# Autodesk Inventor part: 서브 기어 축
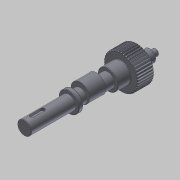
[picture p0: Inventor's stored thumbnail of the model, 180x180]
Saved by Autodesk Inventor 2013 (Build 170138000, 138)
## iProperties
Created: 2018-12
Part Number: 서브 기어 축
Material: 강철, 연강
Document SubType Name: Modeling
Designer: mduedu
Categories: <?xml version="1.0" encoding="UTF-16"?> <MemberInstance><Categories><FamilyTemplate><FamilyTemplateParameter ValueType="xs:double" Id="1" ObjectReferenceKey="da
Density: 1 g/cm^3
Author: mduedu
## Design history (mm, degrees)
sketch "Sketch1"
  geometry: C1 r 21.3 at (0, 0)
  constraints: 1 centre point
  dimensions: "d0" = 42.6 diameter of C1 (= da_da)
extrude "Extrusion1" new body sketch "Sketch1" distance "d1" = 20 (= da_b); taper "d2" = 0 deg
workplane "Work Plane2"
sketch "Sketch2"
  geometry: C1 r 21.3 at (0, 0) reference; C2 r 20.5 at (0, 0)
  constraints: 1 centre point, 1 coincident
  dimensions: "d3" = 41 diameter of C2 (= da_dw)
feature "피치 지름" sketch "Sketch2" dims "d4" = 10, "d5" = 0
workplane "Work Plane8"
workplane "Work Plane9"
chamfer "모따기1" distance "d49" = 1; stored, may be unused: second distance "d50" = 2, angle "d51" = 45 deg
sketch "스케치3"
  geometry: C1 r 12.5 at (0, 0); 1 further point
  constraints: 1 centre point, 1 coincident
  dimensions: "d52" = 25 diameter of C1
extrude "돌출2" join sketch "스케치3" distance "d53" = 16; taper "d54" = 0 deg
sketch "스케치4"
  geometry: C1 r 8.5 at (0, 0); 1 further point
  constraints: 1 centre point, 1 coincident
  dimensions: "d55" = 17 diameter of C1
extrude "돌출3" join sketch "스케치4" distance "d56" = 103; taper "d57" = 0 deg
sketch "스케치5"
  geometry: C1 r 7.5 at (0, 0); 1 further point
  constraints: 1 centre point, 1 coincident
  dimensions: "d58" = 15 diameter of C1
extrude "돌출4" join sketch "스케치5" distance "d59" = 16; taper "d60" = 0 deg
sketch "스케치6"
  geometry: C1 r 4 at (0, 0); 1 further point
  constraints: 1 centre point, 1 coincident
  dimensions: "d61" = 8 diameter of C1
extrude "돌출5" join sketch "스케치6" distance "d62" = 7; taper "d63" = 0 deg
chamfer "모따기2" distance "d64" = 0.5; stored, may be unused: second distance "d65" = 2, angle "d66" = 45 deg
fillet "모깎기1" dims "d67" = 0.5
feature "스퍼 기어" dims "da_b" = 20, "da_d" = 41, "da_aw" = 31, "da_da" = 42.6, "da_df" = 39.086, "da_dw" = 41, angle "da_beta" = 0 deg, "da_lefttooth" = 0, "da_righttooth" = 0
node "작업 평면11"
sketch "스케치7"
  geometry: C1 r 11.5 at (0, 3); C2 r 8.5 at (0, 0) reference; 1 further point
  constraints: 1 centre point, 1 tangent, 1 vertical alignment
  dimensions: "d69" = 3 distance of point (0, 0) C1.centre; "d70" = 23 diameter of C1 (derived)
extrude "돌출6" join sketch "스케치7" stored distance "d71" = 20; taper "d72" = 0 deg
node "작업 평면12"
sketch "스케치8"
  geometry: C1 r 12.5 at (0, 0) reference; C2 r 12.5 at (0, 0) reference; 1 further point
extrude "돌출7" join sketch "스케치8" distance "d74" = 5; taper "d75" = 0 deg
chamfer "모따기3" distance "d76" = 0.5; stored, may be unused: second distance "d77" = 2, angle "d78" = 45 deg
sketch "스케치9"
  geometry: L1 (-8, 139)-(8, 139) reference; L2 (0, 139)-(0, 0); L3 (-8.5, 84)-(-8.5, 138.5) reference; L4 (-8.5, 115)-(0, 115); L5 (-8.5, 115)-(-8.5, 113.5); L6 (-8.5, 113.5)-(-7, 115); L7 (-7, 115)-(-8.5, 115)
  constraints: 10 end point, 4 point on line, 2 perpendicular, 1 collinear, 1 midpoint
  dimensions: "d79" = 24 distance between parallel lines of L4 L1; "d80" = 3 diameter of L5.end L4; "d81" = 45 deg angle of L6 L3
revolve "회전1" sketch "스케치9" stored, may be unused: angle "d82" = 90 deg
sketch "스케치10"
  geometry: L1 (-8.5, 116.5)-(-7, 115) reference; L2 (-8.5, 113.5)-(-7, 115) reference; 2 further points
  constraints: 1 coincident
node "작업점1"
node "작업 평면13"
sketch "스케치11"
  geometry: L1 (-2.5, 93.5)-(-2.5, 80.5); L2 (2.5, 80.5)-(2.5, 93.5); L3 (-8, 103)-(8, 103) reference; A1 r 2.5 centre (0, 93.5) between (2.5, 93.5) and (-2.5, 93.5); A2 r 2.5 centre (0, 80.5) between (-2.5, 80.5) and (2.5, 80.5); 1 further point
  constraints: 4 end point, 4 point on circle, 4 tangent, 2 centre point, 2 vertical alignment, 1 parallel
  dimensions: "d83" = 7 distance edge to line of A1 L3; "d84" = 18 dimension on A2 A1; "d85" = 5 distance between parallel lines of L1 L2
extrude "돌출8" cut sketch "스케치11" distance "d86" = 3; taper "d87" = 0 deg
sketch "스케치12" dims "d88" = 32
  geometry: C1 r 0.5 at (0, -16); 2 further points
  constraints: 2 vertical alignment, 1 centre point, 1 coincident, 2 other
  dimensions: "d89" = 1 diameter of C1
extrude "돌출9" join sketch "스케치12" distance "d90" = 0.3; taper "d91" = 0 deg
sketch "스케치13"
  geometry: C1 r 11.5 at (0, 3) reference; 1 further point
  node "절단 모서리 투영1"
body "Solid1"
body "Srf1"
node "투영된 루프1"
other parameters: "d16" = 31 (= da_aw), "d17" = 0, "d34" = 0.76624 (computed from da_z), "d39" = 0, "d41" = 0, "d43" = 31 (= da_aw), "d46" = 31 (= da_aw), "d47" = 0, "d48" = 0, "d68" = 24, "d73" = 48
